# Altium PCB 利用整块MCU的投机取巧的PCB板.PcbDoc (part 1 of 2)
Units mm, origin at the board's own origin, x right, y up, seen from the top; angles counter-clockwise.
Board outline 162.08 x 191.08 mm, 2 copper layers (Top Layer, Bottom Layer); 156 components, 178 nets, 550 pads, 92 vias.
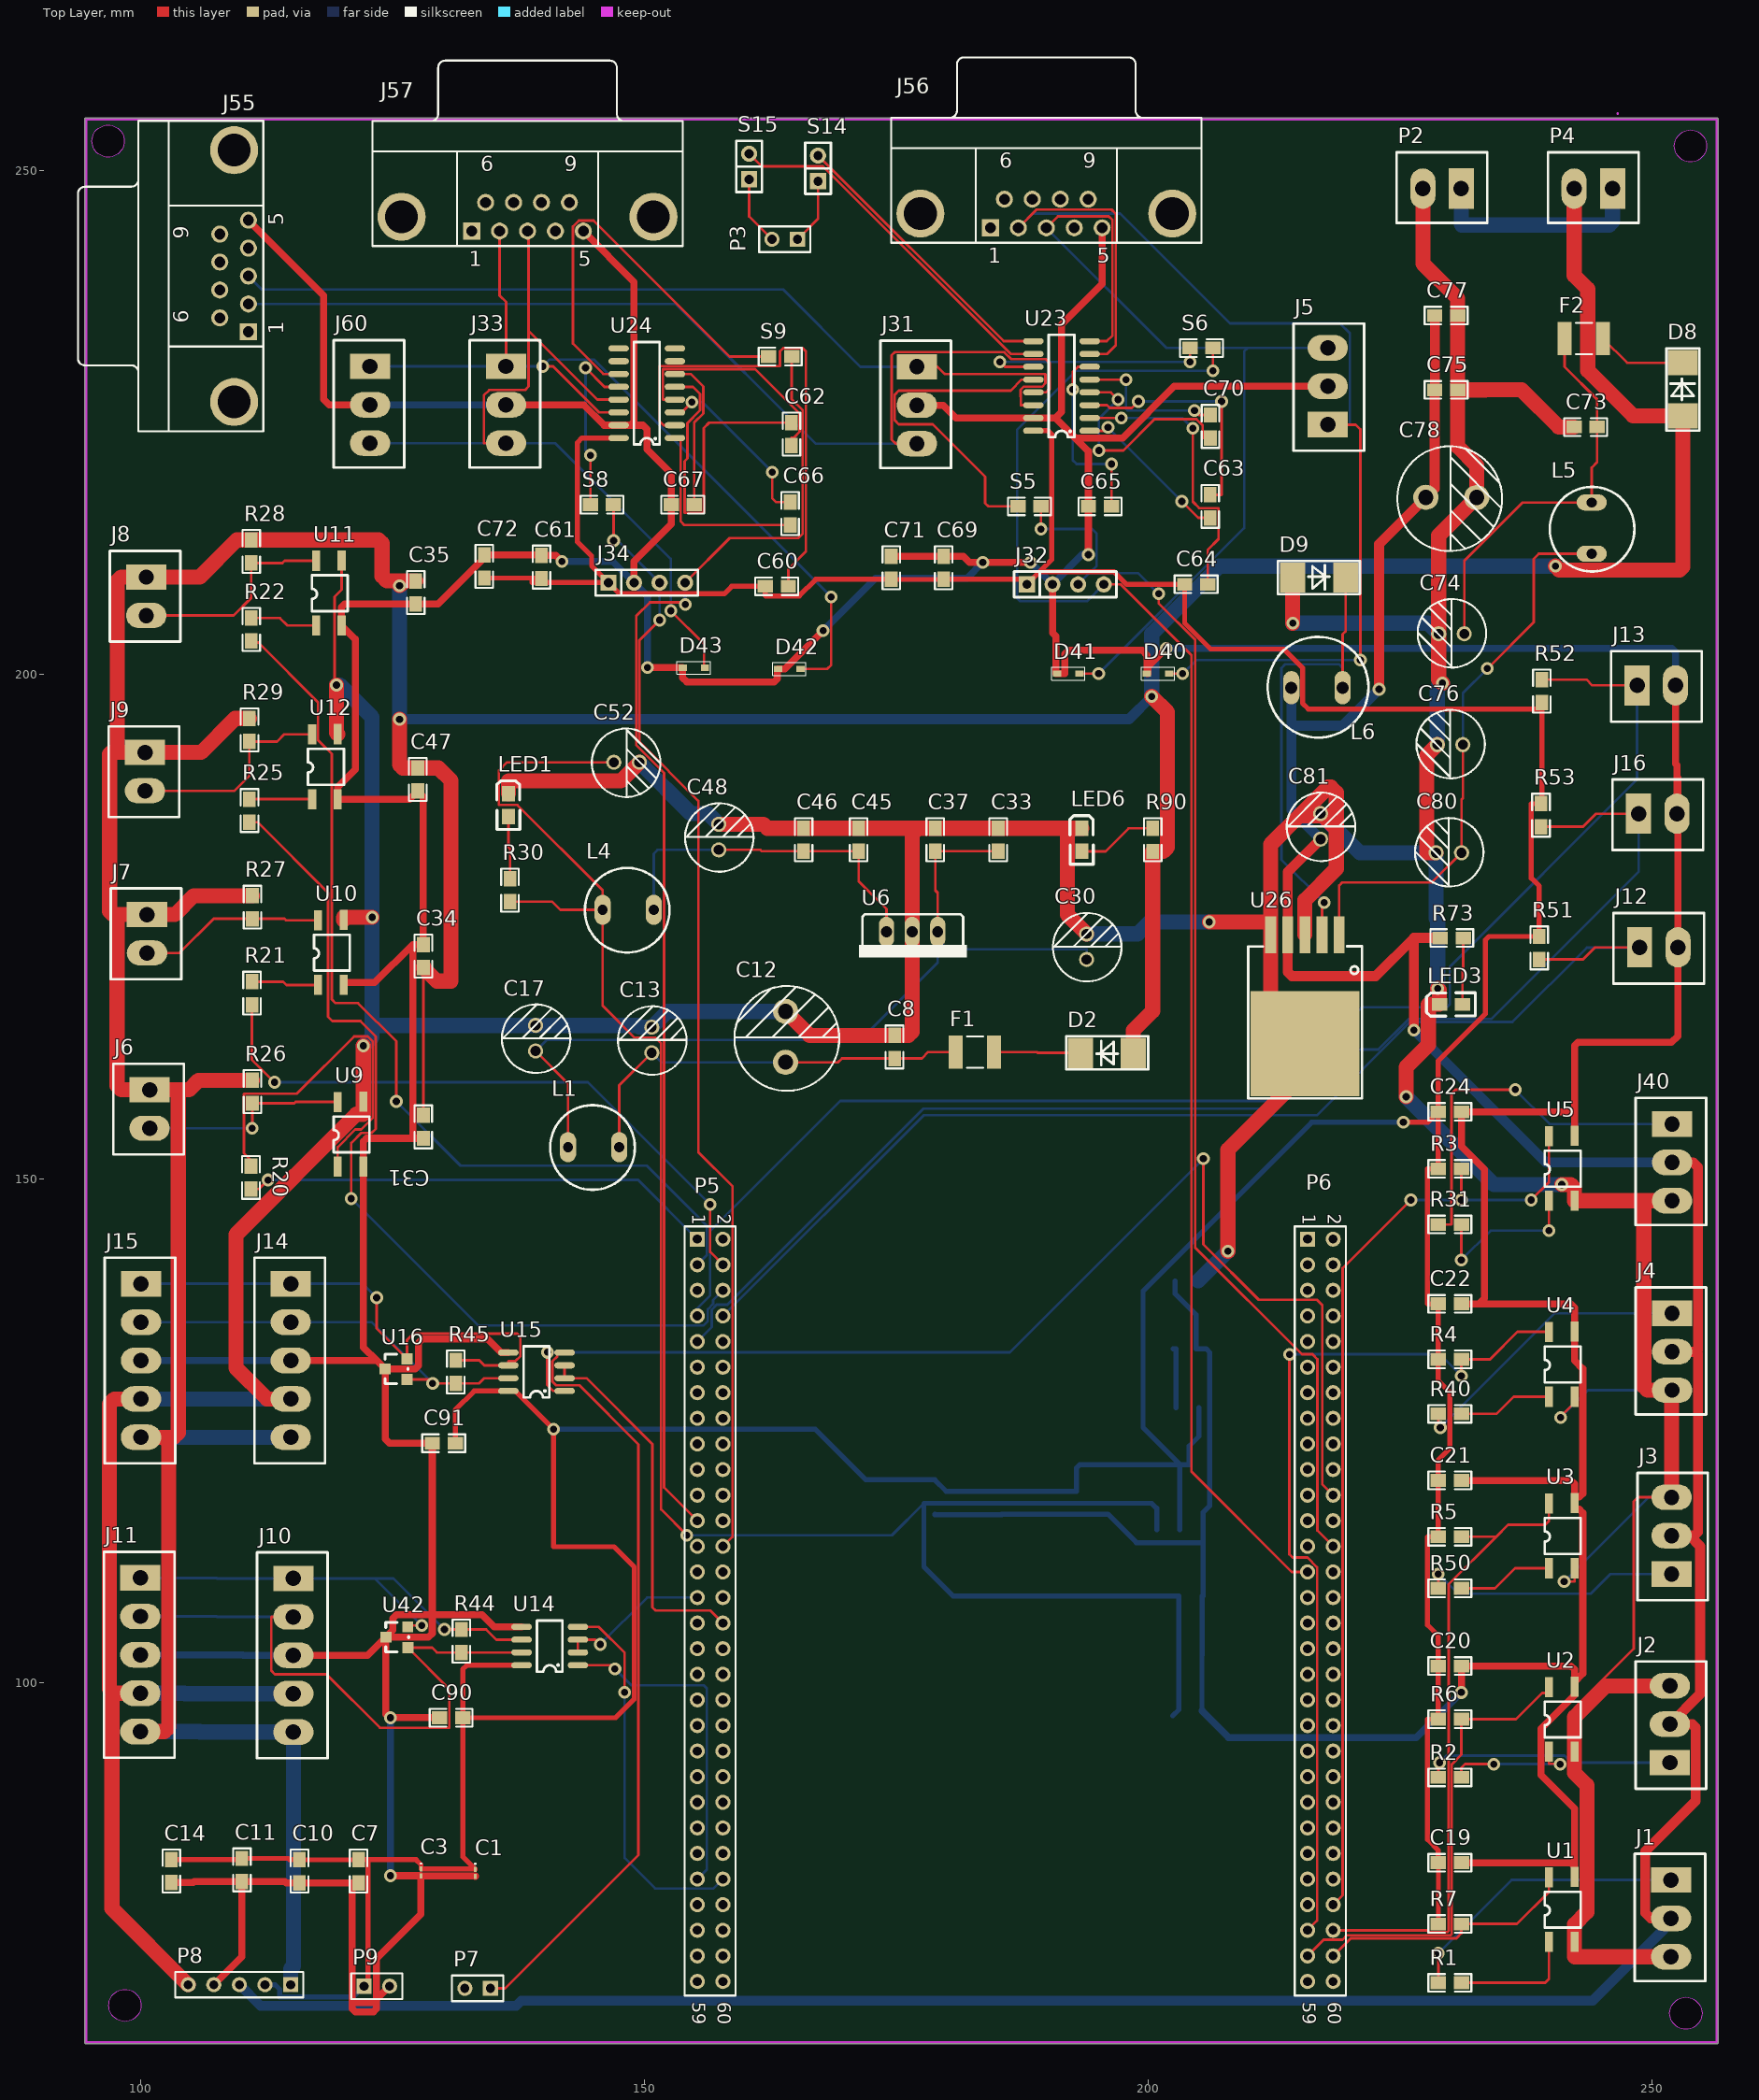
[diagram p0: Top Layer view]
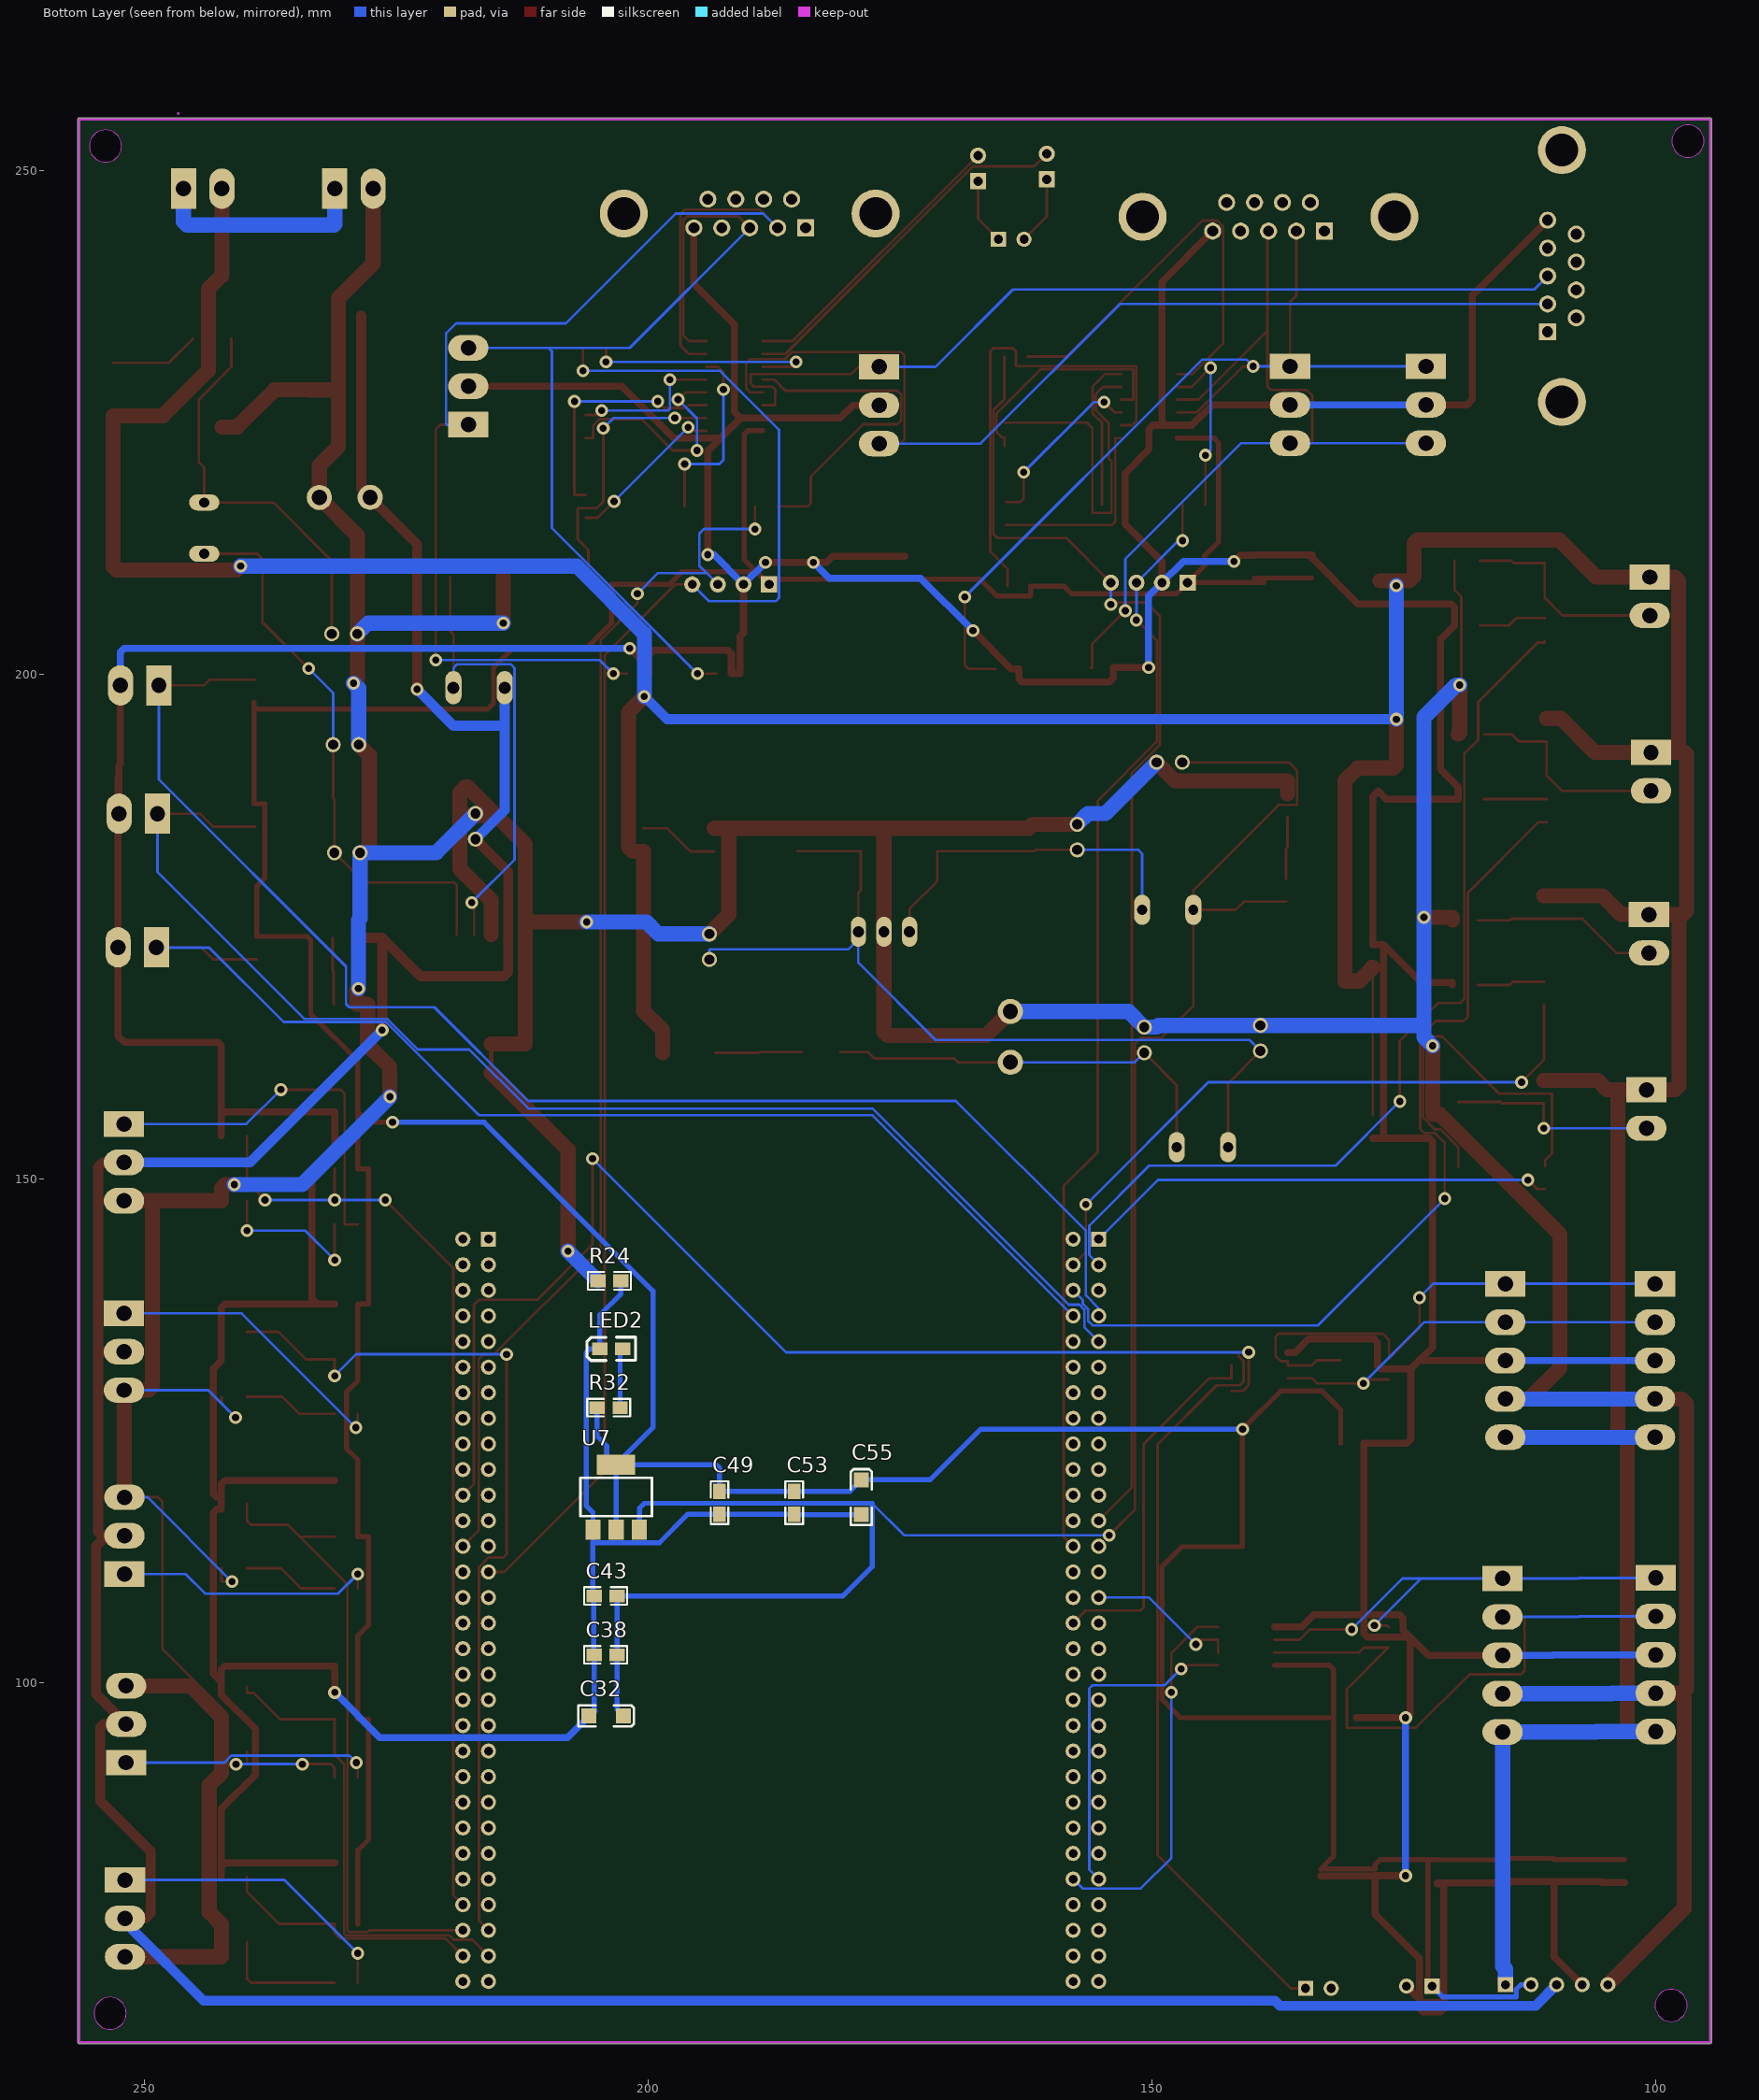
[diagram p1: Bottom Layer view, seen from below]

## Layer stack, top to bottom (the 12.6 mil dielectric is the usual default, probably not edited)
Top Solder: solder mask 0.0102, Solder Resist, Dk 3.5
Top Layer: signal copper 0.0356
Dielectric 1: dielectric 0.32, FR-4, Dk 4.8
Bottom Layer: signal copper 0.0356
Bottom Solder: solder mask 0.0102, Solder Resist, Dk 3.5

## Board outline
94.478,64.292 94.478,255.114 cw(c94.606,255.114) 94.606,255.241 247.44,255.241 cw(c247.446,255.114) 247.446,255.242 256.428,255.242 cw(c256.428,255.114) 256.556,255.114 cw(c256.428,255.114) 256.555,255.103 cw(c256.428,255.093) 256.556,255.093 256.556,64.292 cw(c256.428,64.292) 256.428,64.164 94.606,64.164 cw(c94.606,64.292)
cut-out: 98.47,66.355 cw(c98.47,67.955) 96.87,67.955 cw(c98.47,67.955) 98.47,69.555 cw(c98.47,67.955) 100.07,67.955 cw(c98.47,67.955)
cut-out: 254.955,67.171 cw(c253.355,67.171) 253.355,65.571 cw(c253.355,67.171) 251.755,67.171 cw(c253.355,67.171) 253.355,68.771 cw(c253.355,67.171)
cut-out: 255.417,252.463 cw(c253.817,252.463) 253.817,250.863 cw(c253.817,252.463) 252.217,252.463 cw(c253.817,252.463) 253.817,254.063 cw(c253.817,252.463)
cut-out: 96.804,251.351 cw(c96.804,252.951) 95.204,252.951 cw(c96.804,252.951) 96.804,254.551 cw(c96.804,252.951) 98.404,252.951 cw(c96.804,252.951)

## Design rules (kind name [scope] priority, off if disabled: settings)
Clearance [All] p1: gap=0.051 ignorepadtopadclearanceinfootprint=FALSE except(0: Arc-Hole Track-Hole SMDPad-Hole THPad-Hole Via-Hole Fill-Hole Poly-Hole Region-Hole Text-Hole)
PolygonConnect [All] p1: connectstyle=Relief reliefconductorwidth=0.254 reliefentries=4 polygonreliefangle="90 Angle" airgapwidth=0.254
RoutingVias [All] p1: holewidth=0.711 width=1.27 viastyle="Through Hole" minholewidth=0.711 minwidth=1.27 maxholewidth=0.711 maxwidth=1.27
SolderMaskExpansion [All] p1: expansion=0.102
Width [All] p1: maxlimit=1.5 minlimit=0.254 preferedwidth=0.254 minimp=50.000000 maximp=50.000000 favimp=50.000000
30 further rules are at their usual default settings.

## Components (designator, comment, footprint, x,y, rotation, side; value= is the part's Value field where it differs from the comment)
C1 "10uf/50V 5%" 0603 133.237,81.11 r270 top
C3 "100nf/50V 5%" 0603 127.852,81.141 r270 top
C7 "100nf/50V 5%" 0805C 121.637,82.363 r270 top
C8 "100nf/50V 5%" 0805C 174.856,161.969 r90 top
C10 "100nf/50V 5%" 0805C 115.769,82.363 r270 top
C11 "100nf/50V 5%" 0805C 110.054,82.49 r270 top
C12 "220uf/35V" C10-35V330uf 164.025,161.54 r90 top
C13 "10uf/35V" C6.5-35V47uf 150.743,162.483 r90 top
C14 "100nf/50V 5%" 0805C 103.054,82.387 r270 top
C17 "220uf/35V" C6.5-35V47uf 139.218,162.659 r90 top
C19 "100nf/50V 5%" 0805C 231.03,82.135 r180 top
C20 "100nf/50V 5%" 0805C 231.03,101.651 r180 top
C21 "100nf/50V 5%" 0805C 231.03,120.066 r180 top
C22 "100nf/50V 5%" 0805C 231.03,137.592 r180 top
C24 "100nf/50V 5%" 0805C 231.03,156.642 r180 top
C30 "47uf 50V" C6.5-35V47uf 193.898,171.737 r90 top
C31 "100nf/50V 5%" 0805C 128.098,154.045 r90 top
C32 "16V10uf" 1206-2 204.141,96.68 r180 bottom
C33 "100nf/50V 5%" 0805C 185.142,182.525 r90 top
C34 "100nf/50V 5%" 0805C 128.062,173.174 r270 top
C35 "100nf/50V 5%" 0805C 127.354,207.067 r90 top
C37 "10nf/50V 5%" 0805C 178.901,182.525 r90 top
C38 "100nf/50V 5%" 0805C 203.104,102.764 r0 bottom
C43 "10nf/50V 5%" 0805C 203.104,108.606 r0 bottom
C45 "10nf/50V 5%" 0805C 171.299,182.525 r90 top
C46 "100nf/50V 5%" 0805C 165.838,182.525 r90 top
C47 "100nf/50V 5%" 0805C 127.557,188.51 r90 top
C48 "47uf 50V" C6.5-35V47uf 157.396,182.622 r90 top
C49 "100nf/50V 5%" 0805C 192.913,118.932 r270 bottom
C52 "10uf 50V" C6.5-35V47uf 146.984,191.308 r0 top
C53 "10nf/50V 5%" 0805C 185.503,118.932 r270 bottom
C55 "16V10uf" 1206-2 178.824,118.395 r90 bottom
C60 "100nf/50V 5%" 0805C 162.066,208.753 r0 top
C61 "10uf/50V 5%" 0805C 139.821,209.597 r90 top
C62 "100nf/50V 5%" 0805C 164.59,224.963 r270 top
C63 "100nf/50V 5%" 0805C 206.179,215.615 r90 top
C64 "100nf/50V 5%" 0805C 203.669,208.945 r0 top
C65 "100nf/50V 5%" 0805C 196.308,216.728 r180 top
C66 "100nf/50V 5%" 0805C 164.497,214.897 r90 top
C67 "100nf/50V 5%" 0805C 154.906,216.899 r180 top
C69 "10uf/50V 5%" 0805C 179.737,209.519 r90 top
C70 "100nf/50V 5%" 0805C 206.163,225.729 r270 top
C71 "100nf/50V 5%" 0805C 174.494,211.709 r270 top
C72 "100nf/50V 5%" 0805C 134.108,211.832 r270 top
C73 "100nf/50V 5%" 0805C 244.501,224.602 r180 top
C74 "10uf/35V" C6.5-35V47uf 231.367,204.056 r180 top
C75 "10nf/50V 5%" 0805C 228.479,228.242 r0 top
C76 "220uf/35V" C6.5-35V47uf 231.233,193.06 r180 top
C77 "100nf/50V 5%" 0805C 228.479,235.608 r0 top
C78 "470u/16V" C10-35V330uf 227.555,217.594 r0 top
C80 "10u/35V" C6.5-35V47uf 231.099,182.332 r180 top
C81 "100uf/16V" C6.5-35V47uf 217.108,183.681 r90 top
C90 "100nf/50V 5%" 0805C 129.751,96.482 r0 top
C91 "100nf/50V 5%" 0805C 129.019,123.715 r0 top
D2 "1N5822" SS34 193.793,162.032 r270 top
D8 "1N5822" SS34 252.614,230.441 r180 top
D9 "1N5822" SS34 219.09,210.086 r90 top
D40 "SD12C" SD12C 200.985,200.108 r0 top
D41 "SD12C" SD12C 192.062,200.108 r0 top
D42 "SD12C" SD12C 164.409,200.572 r0 top
D43 "SD12C" SD12C 154.917,200.699 r0 top
F1 "500mA" 1812 182.814,162.56 r180 top
F2 "500mA" 1812 243.231,233.351 r180 top
J1 "CON3" CON-3P-3.81 251.856,80.377 r270 top
J2 "CON3" CON-3P-3.81 251.796,92.07 r90 top
J3 "CON3" CON-3P-3.81 251.963,110.784 r90 top
J4 "CON3" CON-3P-3.81 251.959,136.596 r270 top
J5 "CON3" CON-3P-3.81 217.842,224.838 r90 top
J6 "红色" CON-2P-3.81 100.92,158.803 r270 top
J7 "绿色" CON-2P-3.81 100.666,176.202 r270 top
J8 "黄色" CON-2P-3.81 100.59,209.686 r270 top
J9 "蓝色" CON-2P-3.81 100.463,192.287 r270 top
J10 "Header 5" CON-5P-3.81 115.192,110.268 r270 top
J11 "Header 5" CON-5P-3.81 99.999,110.317 r270 top
J12 "蓝色按键" CON-2P-3.81 248.763,172.947 r0 top
J13 "绿色按键" CON-2P-3.81 248.52,198.944 r0 top
J14 "Header 5" CON-5P-3.81 114.924,139.514 r270 top
J15 "Header 5" CON-5P-3.81 100.065,139.514 r270 top
J16 "绿色按键" CON-2P-3.81 248.662,186.209 r0 top
J31 "CON3" CON-3P-3.81 177.028,230.53 r270 top
J32 "USART4" SIP4 191.784,208.963 r0 top
J33 "CON2" CON-3P-3.81 136.261,230.574 r270 top
J34 "USART2" SIP4 150.255,209.134 r0 top
J40 "CON3" CON-3P-3.81 251.959,155.392 r270 top
J55 "D Connector 9" DSUB1.385-2H9 99.808,239.561 r90 top
J56 "D Connector 9" DSUB1.385-2H9 189.895,255.261 r0 top
J57 "D Connector 9" DSUB1.385-2H9 138.42,254.939 r0 top
J60 "CON3" CON-3P-3.81 122.773,230.574 r270 top
L1 "Inductor" LC-8.2 147.484,153.108 r180 top value="10uH 2A"
L4 "10uH 2A" LC-8.2 150.919,176.653 r180 top
L5 "Inductor" LC-8.2 244.03,217.055 r270 top value="10uH 2A"
L6 "331" LC-10 216.331,198.985 r0 top
LED1 "LED R" 0805D 136.553,185.986 r90 top
LED2 "LED B" 0805D 202.565,133.141 r0 bottom
LED3 "LED G" 0805D 231.11,167.316 r180 top
LED6 "LED B" 0805D 193.439,182.549 r90 top
P2 "Power24V" CON-2P-3.81 231.069,248.236 r180 top
P3 "Header 2" HDR1X2 165.213,243.208 r180 top
P4 "Power24V" CON-2P-3.81 246.079,248.236 r180 top
P5 "Header 30X2" HDR2X30 155.267,143.989 r270 top
P6 "Header 30X2" HDR2X30 215.819,143.989 r270 top
P7 "Header 2" HDR1X2 134.742,69.651 r180 top
P8 "Header 5" HDR1X5 114.911,70.009 r180 top
P9 "Header 2" HDR1X2 122.193,69.866 r0 top
R1 "620R 1%" 0805R 231.055,70.24 r180 top
R2 "620R 1%" 0805R 231.055,90.627 r180 top
R3 "2K 1%" 0805R 231.055,151.015 r180 top
R4 "2K 1%" 0805R 231.055,132.113 r180 top
R5 "2K 1%" 0805R 231.055,114.503 r180 top
R6 "2K 1%" 0805R 231.055,96.405 r180 top
R7 "2K 1%" 0805R 231.055,76.082 r180 top
R20 "620R 1%" 0805R 110.928,151.228 r270 top
R21 "620R 1%" 0805R 111.037,169.516 r270 top
R22 "620R 1%" 0805R 110.961,205.599 r270 top
R24 "0R 1%" 0805R 204.941,139.803 r180 bottom
R25 "620R 1%" 0805R 110.783,187.633 r270 top
R26 "2K 1%" 0805R 111.08,159.737 r270 top
R27 "2K 1%" 0805R 111.08,178.048 r270 top
R28 "2K 1%" 0805R 110.961,213.346 r270 top
R29 "2K 1%" 0805R 110.783,195.634 r270 top
R30 "10k 1%" 0805R 136.637,179.74 r270 top
R31 "620R 1%" 0805R 231.055,145.491 r180 top
R32 "10K 1%" 0805R 202.777,127.318 r0 bottom
R40 "620R 1%" 0805R 231.055,126.695 r180 top
R44 "120R 1%" 0805R 131.905,103 r90 top
R45 "120R 1%" 0805R 131.348,129.707 r90 top
R50 "620R 1%" 0805R 231.055,109.38 r180 top
R51 "2K 1%" 0805R 238.756,174.007 r270 top
R52 "2K 1%" 0805R 239.11,197.254 r90 top
R53 "2K 1%" 0805R 238.933,187.176 r270 top
R73 "10K 1%" 0805R 231.243,173.918 r180 top value=10K
R90 "47K 1%" 0805R 200.404,184.726 r270 top
S5 "0R 1%" 0805R 189.348,216.753 r180 top
S6 "0R 1%" 0805R 206.417,232.46 r180 top
S8 "0R 1%" 0805R 146.93,216.924 r180 top
S9 "0R 1%" 0805R 164.608,231.615 r180 top
S14 "KEY-9" SIP2 167.244,250.245 r90 top
S15 "KEY-9" SIP2 160.413,250.43 r90 top
U1 "TLP181" TLP-181 239.77,74.252 r90 top
U2 "TLP181" TLP-181 239.77,93.124 r90 top
U3 "TLP181" TLP-181 239.77,111.336 r90 top
U4 "TLP181" TLP-181 239.77,128.354 r90 top
U5 "TLP181" TLP-181 239.77,147.785 r90 top
U6 "ZLG K7805-500" TO-220 175.77,174.513 r180 top
U7 "LM1117-3.3" SOT-223 202.791,118.142 r180 bottom
U9 "TLP181" TLP-181 119.589,151.175 r90 top
U10 "TLP181" TLP-181 117.633,169.209 r90 top
U11 "TLP181" TLP-181 117.43,204.883 r90 top
U12 "TLP181" TLP-181 117.049,187.656 r90 top
U14 "SP3485" SO-8 140.625,103.612 r180 top
U15 "SP3485" SO-8 139.306,130.827 r180 top
U16 "SM712" SM712 127.222,128.997 r90 top
U23 "MAX3232" SO-16 191.405,228.65 r180 top
U24 "MAX3232" SO-16 150.257,227.932 r180 top
U26 "LM2596-5" TO-263-5 215.53,163.842 r180 top
U42 "SM712" SM712 127.292,102.383 r90 top

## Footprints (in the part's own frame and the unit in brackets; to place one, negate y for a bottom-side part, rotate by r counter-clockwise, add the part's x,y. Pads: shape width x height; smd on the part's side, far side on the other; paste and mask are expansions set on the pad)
0603 [mm] "Chip Inductor, Body 0.6x0.3mm, IPC High Density"
  rect 0.5x0.3 smd: 1(-0.35,0) 2(0.35,0)
  silkscreen extent -0.9,-0.05 -0.9,0.05, body extent -0.33,-0.18 0.33,0.18, height 0.55
0805C [mil]
  rect 60x50 smd: 1(-1.89,0.71) 2(88.11,0.71)
  silkscreen extent -41,-34 127,35
0805D [mil]
  rect 60x50 smd: 1(-3.11,0.95) 2(86.89,0.95)
  silkscreen extent -53,-44 137,47
0805R [mil]
  rect 60x50 smd: 1(-0.9,1.69) 2(89.1,1.69)
  silkscreen extent -40,-33 128,36
1206-2 [mm]
  rect 1.5x1.5 smd: 1(1.714,0) 2(-1.715,0)
  silkscreen extent -2.76,-1.05 2.76,1.05
1812 [mm] "Chip Capacitor, Body 4.5x3.2mm, IPC High Density"
  rect 1.4x3.3 smd: 1(-1.9,0) 2(1.9,0)
  silkscreen extent -0.8,-1.55 0.8,1.55, body extent -2.4,-1.7 2.4,1.7, height 1.4
C6.5-35V47uf [mm]
  round 1.5 hole 1: 1(0,0) 2(2.54,0)
  silkscreen extent -2.18,-3.45 4.62,3.35
C10-35V330uf [mm]
  round 2.5 hole 1.5: 1(0,0) 2(5.044,-0.009)
  silkscreen extent -2.83,-5.33 7.57,5.07
CON-2P-3.81 [mm]
  rect 2.5x4 hole 1.524: 1(0,0)
  oval 2.5x4 hole 1.524: 2(3.81,0)
  silkscreen extent -2.59,-3.61 6.41,3.39
CON-3P-3.81 [mil]
  rect 100x157.48 hole 60: 1(-1,1)
  oval 100x157.48 hole 60: 2(149,1) 3(299,1)
  silkscreen extent -103,-141 394,135
CON-5P-3.81 [mil]
  rect 100x157.48 hole 60: 1(-2,0)
  oval 100x157.48 hole 60: 2(148,0) 3(298,0) 4(448,0) 5(598,0)
  silkscreen extent -104,-142 700,134
DSUB1.385-2H9 [mm] "Connector; D Subminiature; 9 Position; Right Angle; Pitch 1.385 mm"
  rect 1.69x1.69 hole 1.09: 1(-5.54,-10.92)
  round 1.69 hole 1.09: 2(-2.77,-10.92) 3(0,-10.92) 4(2.77,-10.92) 5(5.54,-10.92) 6(-4.155,-8.08) 7(-1.385,-8.08) 8(1.385,-8.08) 9(4.155,-8.08)
  round 4.76 hole 3.26: 10(-12.495,-9.5) 11(12.495,-9.5)
  silkscreen extent -15.4,-12.4 15.4,6
HDR1X2 [mm] "Connector; Header; 2 Position"
  rect 1.5x1.5 hole 0.9: 1(0,0)
  round 1.5 hole 0.9: 2(2.54,0)
  silkscreen extent -1.27,-1.27 3.81,1.27
HDR1X5 [mm] "Connector; Header; 5 Position"
  rect 1.5x1.5 hole 0.9: 1(0,0)
  round 1.5 hole 0.9: 2(2.54,0) 3(5.08,0) 4(7.62,0) 5(10.16,0)
  silkscreen extent -1.27,-1.27 11.43,1.27
HDR2X30 [mm] "Connector; Header; 30x2 Position"
  rect 1.5x1.5 hole 0.9: 1(0,0)
  round 1.5 hole 0.9: 2(0,2.54) 3(2.54,0) 4(2.54,2.54) 5(5.08,0) 6(5.08,2.54) 7(7.62,0) 8(7.62,2.54) 9(10.16,0) 10(10.16,2.54) 11(12.7,0) 12(12.7,2.54) 13(15.24,0) 14(15.24,2.54) 15(17.78,0) 16(17.78,2.54) 17(20.32,0) 18(20.32,2.54) 19(22.86,0) 20(22.86,2.54) 21(25.4,0) 22(25.4,2.54) 23(27.94,0) 24(27.94,2.54) 25(30.48,0) 26(30.48,2.54) 27(33.02,0) 28(33.02,2.54) 29(35.56,0) 30(35.56,2.54) 31(38.1,0) 32(38.1,2.54) 33(40.64,0) 34(40.64,2.54) 35(43.18,0) 36(43.18,2.54) 37(45.72,0) 38(45.72,2.54) 39(48.26,0) 40(48.26,2.54) 41(50.8,0) 42(50.8,2.54) 43(53.34,0) 44(53.34,2.54) 45(55.88,0) 46(55.88,2.54) 47(58.42,0) 48(58.42,2.54) 49(60.96,0) 50(60.96,2.54) 51(63.5,0) 52(63.5,2.54) 53(66.04,0) 54(66.04,2.54) 55(68.58,0) 56(68.58,2.54) 57(71.12,0) 58(71.12,2.54) 59(73.66,0) 60(73.66,2.54)
  silkscreen extent -1.27,-1.27 75.06,3.81
LC-8.2 [mm]
  oval 1.6x3 hole 1: 1(-0.034,-0.017) 2(5.046,-0.017)
  silkscreen extent -1.59,-4.17 6.81,4.22
LC-10 [mm]
  oval 1.6x3.3 hole 1.2: 1(-2.117,-0.271) 2(2.963,-0.271)
  silkscreen extent -4.47,-5.23 5.53,4.77
SD12C [mm]
  rect 0.83x0.63 smd: 1(-1.11,0) 2(1.11,0)
  silkscreen extent -1.65,-0.63 1.65,0.64
SIP2 [mil]
  rect 63x63 hole 36: 1(-50,0)
  round 63 hole 36: 2(50,0)
  silkscreen extent -100,-50 100,50
SIP4 [mil]
  rect 63x63 hole 36: 1(-150,0)
  round 63 hole 36: 2(-50,0) 3(50,0) 4(150,0)
  silkscreen extent -200,-50 200,50
SM712 [mm]
  rect 1.1x1.1 smd: 1(1.068,0.743) 2(3.128,0.763) 3(2.118,2.923)
  silkscreen extent 0.65,0.66 3.57,2.95
SO-8 [mil]
  oval 80x24 smd: 1(-110,75) 2(-110,25) 3(-110,-25) 4(-110,-75) 5(110,-75) 6(110,-25) 7(110,25) 8(110,75)
  silkscreen extent -50,-100 50,100
SO-16 [mil]
  oval 80x24 smd: 1(-110,175) 2(-110,125) 3(-110,75) 4(-110,25) 5(-110,-25) 6(-110,-75) 7(-110,-125) 8(-110,-175) 9(110,-175) 10(110,-125) 11(110,-75) 12(110,-25) 13(110,25) 14(110,75) 15(110,125) 16(110,175)
  silkscreen extent -50,-200 50,200
SOT-223 [mil]
  rect 59x79 smd: 1(-104.55,-116.77) 2(-14,-116.77) 3(76.55,-116.77)
  rect 150x79 smd: 2(-14.67,136.78)
  silkscreen extent -154,-65 126,85
SS34 [mm]
  rect 3x2.5 smd: 1(-0.44,4.743) 2(-0.44,-0.517)
  silkscreen extent -2.08,-1.93 1.19,6.22
TLP-181 [mm]
  rect 2x0.8 smd: 1(0,0) 2(0,-2.54) 3(6.452,-2.54) 4(6.426,0)
  silkscreen extent 1.42,-3.15 4.98,0.41
TO-220 [mm]
  oval 1.5x3 hole 1.1: 1(-3.35,0.025) 2(-0.805,0.029) 3(1.735,0.029)
  silkscreen extent -6.27,-1.72 4.45,2.6
TO-263-5 [mm]
  rect 1.07x3.66 smd: 1(-3.425,-10.36) 2(-1.725,-10.36) 3(-0.025,-10.36) 4(1.675,-10.36) 5(3.375,-10.36)
  rect 10.8x10.41 smd: 3(-0.025,0.465)
  silkscreen extent -5.69,-9.21 5.59,5.89

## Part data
C1 C3 C7 C8 C10 C11 C14 C19 C20 C21 C22 C24 C31 C33 C34 C35 C37 C38 C43 C45 C46 C47 C49 C53 C60 C61 C62 C63 C64 C65 C66 C67 C69 C70 C71 C72 C73 C75 C77 C90 C91: library part CAP, "Capacitor"
C12 C13 C17 C30 C48 C52 C74 C76 C78 C80 C81: library part "CAPACITOR POL", "Capacitor"
C32 C55: library part CAP+
D2 D8 D9 D40 D41 D42 D43: library part DIODE, "Diode"
F1 F2: library part "Fuse 1", "Fuse"
J1 J2 J3 J4 J5 J31 J40 J60: "Connector"
J6 J7 J8 J9 J12 J13 J16 P2 P4: library part CON2, "Connector"
J10 J11 J14 J15 P8: "Header, 5-Pin"
J32 J34: library part CON4, "Connector"
J33: library part CON3, "Connector"
J55 J56 J57: "Receptacle Assembly, 9 Position, Right Angle", PackageDocument=O
L4: library part INDUCTOR1
L6: library part INDUCTOR
LED1 LED2 LED3 LED6: library part LED
P3 P7 P9: "Header, 2-Pin"
P5 P6: "Header, 30-Pin, Dual row"
R1 R2 R3 R4 R5 R6 R7 R20 R21 R22 R24 R25 R26 R27 R28 R29 R30 R31 R32 R40 R44 R45 R50 R51 R52 R53 R90: library part RES2
R73: library part Res1, "Resistor"
S5 S6 S8 S9: library part RES
S14 S15: library part KEY-2
U1 U2 U3 U4 U5 U9 U10 U11 U12: library part TLP521-1
U6: library part VOLTREG
U7: library part LM1117
U14 U15: library part MAX485
U26: library part LM2596-5.0

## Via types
v1: diameter 1.27, hole 0.711, Top Layer to Bottom Layer, 92 vias

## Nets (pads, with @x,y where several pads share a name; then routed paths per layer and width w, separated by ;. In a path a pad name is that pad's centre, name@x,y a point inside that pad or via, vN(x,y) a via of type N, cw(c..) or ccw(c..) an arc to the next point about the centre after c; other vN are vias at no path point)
3V3: C1.1 C3.1 C7.1 C10.1 C11.1 C14.1 C19.2 C20.2 C21.2 C22.2 C24.2 C49.1 C53.1 C55.1 C60.1 C61.1 C64.1 C69.1 C71.2 C72.2 C90.2 C91.2 J32.1 J34.1 P8.2 P9.1 R3.2 R4.2 R5.2 R6.2 R7.2 R32.2 R51.1 R52.1 R53.1 U7.2 U14.8 U15.8 U23.16 U24.16 | length 576.5
  Top Layer w0.5: C14.1@103.072,82.435 110.072,82.435 C11.1@110.072,82.538 114.681,82.538 114.808,82.411 C10.1@115.787,82.411 115.787,82.398 121.655,82.398 C7.1@121.655,82.411 122.58,82.411 ; P9.1@122.193,69.866 122.606,70.278 122.606,82.386 122.58,82.411 ; C3.1@127.852,81.491 C3.1@127.852,81.509 ; C91.2@131.257,123.733 131.257,127.057 133.121,128.922 U15.8@136.512,128.922 137.211,128.922 v1(140.995,125.137) 140.995,113.473 147.004,113.473 149,111.477 149,98.338 147.162,96.5 C90.2@131.989,96.5 ; C72.2@134.126,209.594 139.803,209.594 C61.1@139.803,209.549 138.887,209.549 138.862,209.523 138.862,209.159 138.887,209.134 J34.1@146.445,209.134 ; U14.8@137.831,101.707 132.398,101.707 131.989,101.299 C90.2@131.989,96.5 ; U24.16@147.463,223.487 143.827,223.487 143.383,223.043 143.383,213.182 144.78,211.785 144.78,210.799 J34.1@146.445,209.134 ; U23.16@188.611,224.205 190.082,224.205 190.449,223.837 190.449,211.438 189.222,210.21 ; v1(225.332,155.585) 227.753,155.585 C24.2@228.792,156.625 ; R7.2@228.792,76.039 228.803,76.039 228.803,82.117 C19.2@228.792,82.117 228.792,83.337 227.711,84.418 227.711,96.337 227.736,96.363 R6.2@228.778,96.363 ; R6.2@228.792,96.363 R6.2@228.778,96.363 ; 122.58,82.411 127.356,82.411 127.852,81.915 C3.1@127.852,81.509 ; C3.1@127.852,81.509 C1.1@133.188,81.509 ; C90.2@131.989,96.5 131.989,82.708 C1.1@133.188,81.509 ; C1.1@133.188,81.509 133.237,81.509 C1.1@133.237,81.46 C1.1@133.188,81.509 ; J34.1@146.445,209.134 147.553,208.026 157.937,208.026 158.682,208.771 C60.1@162.018,208.771 162.018,207.848 162.044,207.823 165.379,207.823 167.027,209.471 C71.2@174.512,209.471 174.512,209.448 179.719,209.448 C69.1@179.719,209.471 187.466,209.471 J32.1@187.974,208.963 189.222,210.21 ; 189.222,210.21 196.621,210.21 197.869,208.963 C64.1@203.621,208.963 203.621,205.116 206.197,202.54 213.462,202.54 215.316,200.685 215.316,197.167 215.887,196.596 239.067,196.596 R52.1@239.067,197.231 239.09,197.231 239.09,187.199 R53.1@238.976,187.199 238.049,187.199 238.023,187.173 238.023,179.807 238.799,179.031 R51.1@238.799,174.03 233.809,174.03 233.451,173.672 233.451,166.345 228.792,161.685 C24.2@228.792,156.625 ; R6.2@228.778,96.363 228.778,101.634 C20.2@228.792,101.634 228.792,104.623 227.711,105.703 227.711,114.435 227.736,114.461 R5.2@228.792,114.461 C21.2@228.792,120.049 228.792,122.072 229.921,123.201 229.921,128.803 228.792,129.932 R4.2@228.792,132.071 228.778,132.071 228.778,133.438 228.792,133.452 C22.2@228.792,137.575 227.736,137.575 227.711,137.6 227.711,150.946 227.736,150.972 R3.2@228.792,150.972 C24.2@228.792,156.625
  Bottom Layer w0.5: P8.2@112.371,70.009 113.366,70.009 113.843,69.532 113.843,68.809 113.868,68.783 121.111,68.783 P9.1@122.193,69.866 ; v1(140.995,125.137) 166.963,125.137 171.991,120.109 C55.1@178.824,120.109 179.954,118.98 C53.1@185.485,118.98 185.485,118.974 192.895,118.974 C49.1@192.895,118.98 192.895,121.285 193.226,121.616 U7.2@203.147,121.616 ; U7.2@203.147,115.176 U7.2@203.147,121.616 ; R32.2@205.04,127.275 205.04,124.435 204.064,123.458 204.064,121.616 U7.2@203.164,121.616 ; v1(225.332,155.585) 216.23,155.585 199.492,138.847 199.492,125.287 U7.2@203.164,121.616 ; U7.2@203.147,121.616 U7.2@203.164,121.616
5V: C75.1 C77.1 C78.1 C81.1 J1.2 J2.2 J3.2 J4.2 J40.2 L6.1 P8.3 R73.2 U26.4 | length 375.5
  Top Layer w1: C81.1@217.108,183.681 213.856,180.429 U26.4@213.856,174.202 213.856,170.498 214.275,170.078 222.569,170.078 226.365,173.875 226.695,173.875 ; v1(222.91,198.552) 222.91,212.95 C78.1@227.555,217.594 228.431,218.47 C75.1@228.431,228.26 228.448,228.26 228.448,235.626 C77.1@228.431,235.626 ; v1(226.365,164.719) 226.365,173.544 226.695,173.875 ; R73.2@228.98,173.875 226.695,173.875 ; J1.2@251.881,76.592 249.873,76.592 249.326,77.138 249.326,83.236 254.33,88.24 254.33,95.524 254,95.855 J2.2@251.771,95.855 254.767,98.851 254.767,113.52 J3.2@253.719,114.569 ; J3.2@251.938,114.569 J3.2@253.719,114.569 ; J4.2@251.984,132.812 254.381,132.812 ; J40.2@251.984,151.608 254.081,151.608 254.559,151.13 254.559,132.989 254.381,132.812 ; J3.2@253.719,114.569 254.192,114.569 254.559,114.935 254.559,132.634 254.381,132.812
  Bottom Layer w1: P8.3@109.831,70.009 111.921,67.92 137.287,67.92 137.795,68.428 244.094,68.428 251.155,75.489 251.155,76.592 J1.2@251.881,76.592 ; L6.1@214.214,198.714 214.214,195.262 ; C81.1@217.108,183.681 214.214,186.575 214.214,195.262 ; v1(222.91,198.552) 219.304,194.945 214.531,194.945 214.214,195.262 ; v1(226.365,164.719) 239.476,151.608 J40.2@251.984,151.608
24V: C31.2 C34.2 C35.2 C47.2 D2.1 D8.1 J6.1 J7.1 J8.1 J9.1 J10.5 J11.5 J14.5 J15.5 P4.2 P8.1 R26.1 R27.1 R28.1 R29.1 R90.2 | length 537.1
  Top Layer w0.254: C31.2@128.08,156.283 C34.2@128.08,170.936
  Top Layer w1.5: J11.5@99.999,95.128 102.379,95.128 102.819,95.567 102.819,123.825 102.319,124.325 ; J15.5@100.065,124.325 102.319,124.325 ; R29.1@110.826,195.657 109.398,195.657 106.028,192.287 J9.1@100.463,192.287 98.108,192.287 ; R26.1@111.123,159.76 105.783,159.76 104.826,158.803 103.389,158.803 ; R27.1@111.123,178.071 105.298,178.071 103.429,176.202 J7.1@100.666,176.202 98.108,176.202 ; v1(125.73,195.58) 125.73,191.065 126.047,190.748 C47.2@127.539,190.748 129.575,190.748 130.834,189.489 130.834,169.592 129.424,169.592 128.176,170.84 128.176,170.936 C34.2@128.08,170.936 ; v1(125.73,208.839) 126.196,209.305 ; C35.2@127.336,209.305 126.196,209.305 ; D2.1@198.536,162.472 198.536,164.719 200.447,166.63 R90.2@200.447,182.463 201.488,182.463 201.905,182.88 201.905,196.291 v1(200.355,197.841) ; v1(240.411,210.769) 240.792,210.388 252.73,210.388 253.054,210.712 D8.1@253.054,225.697 248.107,225.697 243.611,230.193 243.611,238.277 242.269,239.62 P4.2@242.269,248.236 ; 98.108,176.202 97.278,176.202 96.95,176.53 96.95,192.098 97.139,192.287 98.108,192.287 ; 98.108,176.202 97.688,175.782 97.688,159.222 98.108,158.803 J6.1@100.92,158.803 103.389,158.803 ; 98.108,192.287 97.714,192.681 97.714,209.292 98.108,209.686 J8.1@100.59,209.686 105.893,209.686 109.576,213.369 R28.1@111.004,213.369 123.651,213.369 123.977,213.042 123.977,209.788 124.46,209.305 126.196,209.305 ; 102.319,124.325 103.306,124.325 103.759,124.777 103.759,158.433 103.389,158.803
  Bottom Layer w1: v1(125.73,195.58) 198.095,195.58 v1(200.355,197.841)
  Bottom Layer w1.5: J11.5@99.999,95.128 105.862,95.128 105.912,95.078 J10.5@115.189,95.078 ; J15.5@100.065,124.325 J14.5@114.924,124.325 ; P8.1@114.911,70.009 114.911,71.581 115.189,71.859 J10.5@115.189,95.078 ; J10.5@115.192,95.078 J10.5@115.189,95.078 ; v1(125.73,195.58) v1(125.73,208.839) ; v1(200.355,197.841) 200.355,204.064 207.061,210.769 v1(240.411,210.769)
232_Rxd2: D43.2 J33.3 J57.3 J60.3 U24.13 | length 85.9
  Top Layer w0.254: J33.3@136.287,222.979 134.112,222.979 134.087,223.004 134.087,227.711 134.62,228.244 138.176,228.244 138.532,228.6 138.532,234.109 ; J57.3@138.42,244.019 138.532,244.019 138.532,234.109 ; U24.13@147.463,227.297 145.343,227.297 138.532,234.109 ; v1(152.629,206.35) 155.931,203.048 155.931,200.699 D43.2@156.027,200.699
  Bottom Layer w0.254: J60.3@122.799,222.979 J33.3@136.287,222.979 141.143,222.979 152.629,211.493 v1(152.629,206.35)
232_Rxd4: J31.3 J55.2 U23.13 | length 103.7
  Top Layer w0.254: J31.3@177.054,222.935 174.942,222.935 174.549,223.329 174.549,231.699 174.854,232.004 185.725,232.004 186.411,231.318 189.865,231.318 190.246,230.937 190.246,228.396 189.865,228.015 U23.13@188.611,228.015
  Bottom Layer w0.254: J55.2@110.728,236.791 153.15,236.791 167.006,222.935 J31.3@177.054,222.935
232_Txd2: D42.2 J33.1 J57.2 J60.1 U24.14 | length 88.8
  Top Layer w0.254: J57.2@135.65,244.019 135.65,237.619 136.287,236.982 J33.1@136.287,230.599 ; v1(139.936,230.599) 140.952,230.599 145.524,226.027 U24.14@147.463,226.027 ; D42.2@165.519,200.572 168.149,200.572 168.554,200.977 v1(168.554,207.713)
  Bottom Layer w0.254: J60.1@122.799,230.599 J33.1@136.287,230.599 v1(139.936,230.599) 140.612,231.275 144.992,231.275 v1(168.554,207.713)
232_Txd4: J31.1 J55.3 U23.14 | length 89.5
  Top Layer w0.254: J31.1@177.054,230.555 179.095,230.555 179.806,229.845 189.814,229.819 189.814,228.917 189.471,228.575 187.642,228.575 187.35,228.282 187.376,226.745 U23.14@188.611,226.745
  Bottom Layer w0.254: J55.3@110.728,239.561 112.062,238.227 163.778,238.227 171.45,230.555 J31.1@177.054,230.555
485_A: J10.1 J11.1 R44.2 U14.6 U42.2 | length 48.4
  Top Layer w0.254: U42.2@126.529,105.511 126.682,105.664 v1(127.914,105.664) ; v1(130.175,105.263) R44.2@131.862,105.263 134.315,105.263 135.331,104.247 U14.6@137.831,104.247
  Bottom Layer w0.254: J11.1@99.999,110.368 107.569,110.368 107.618,110.318 J10.1@115.192,110.318 123.26,110.318 ; v1(127.914,105.664) 123.26,110.318 ; v1(130.175,105.263) 125.12,110.318 123.26,110.318
485_A1: J14.1 J15.1 R45.2 U15.6 U16.2 | length 53.9
  Top Layer w0.254: v1(123.444,138.176) 123.444,135.139 U16.2@126.459,132.125 126.459,133.99 127.089,134.62 137.401,134.62 137.719,134.302 137.719,132.398 137.198,131.877 136.537,131.877 136.512,131.851 U15.6@136.512,131.462 134.137,131.462 133.629,131.97 R45.2@131.305,131.97
  Bottom Layer w0.254: J15.1@100.065,139.565 J14.1@114.924,139.565 122.055,139.565 v1(123.444,138.176)
485_B: J10.2 J11.2 R44.1 U14.7 U42.1 | length 63.8
  Top Layer w0.254: J10.2@115.192,106.508 113.03,106.508 113.005,106.483 113.005,101.155 113.347,100.813 118.466,100.813 123.774,95.504 130.632,95.504 130.658,95.529 130.658,99.342 U42.1@126.549,103.451 128.956,103.451 129.43,102.977 R44.1@131.862,102.977 U14.7@137.831,102.977
  Bottom Layer w0.254: J11.2@99.999,106.558 107.569,106.558 107.618,106.508 J10.2@115.192,106.508
485_B1: J14.2 J15.2 R45.1 U15.7 U16.1 | length 41.9
  Top Layer w0.254: U16.1@126.479,130.065 128.676,130.065 v1@129.057,129.684 ; v1(129.007,129.684) v1@129.057,129.684 ; U15.7@136.512,130.192 134.137,130.192 133.629,129.684 R45.1@131.305,129.684 v1@129.057,129.684
  Bottom Layer w0.254: J15.2@100.065,135.755 J14.2@114.924,135.755 122.936,135.755 v1(129.007,129.684)
D+: P6.33
D-: P6.34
